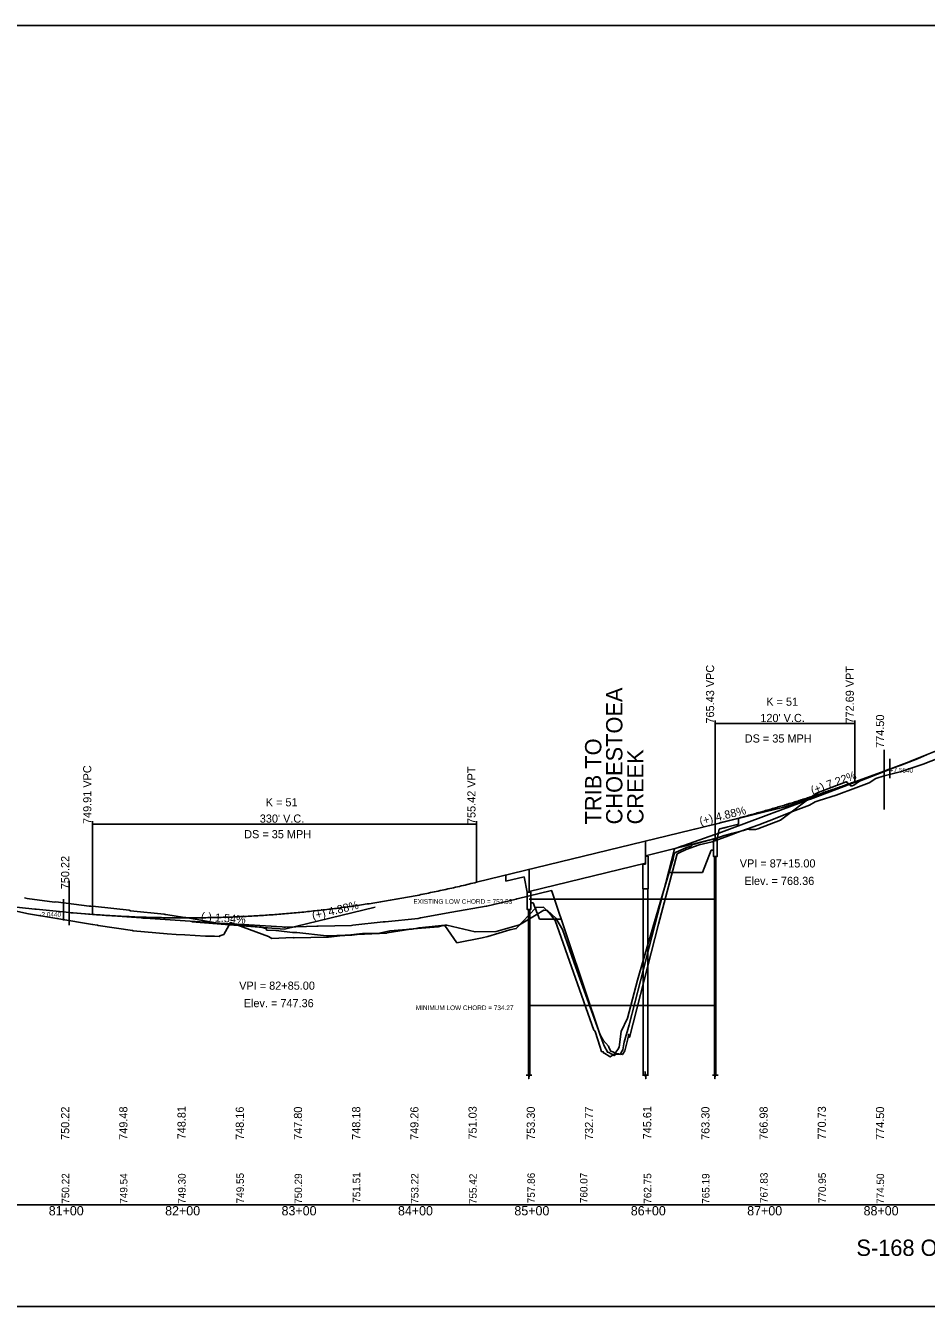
# Model space of a CAD drawing. Extents: x 1384070 to 1387149, y 1001217 to 1002317.
# Drawn here: x 1385108 to 1385882, y 1001217 to 1002317 of the extents above; entities that cross this region are included whole.
import ezdxf

# ---------------------------------------------------------------- set-up
doc = ezdxf.new("R2010")
doc.units = 0
for name, color, linetype in [('BR_EXIST_GROUND_LT', 7, 'Continuous'), ('BR_EXIST_GROUND_RT', 7, 'Continuous'), ('BR_GROUND LINES', 7, 'Continuous'), ('BR_USER NOTES', 7, 'Continuous'), ('RD_DDB_GradeTX', 7, 'Continuous'), ('RD_DDB_Profile_EX', 7, 'Continuous'), ('RD_DDB_Profile_Lbl', 7, 'Continuous'), ('RD_DDB_Profile_PR', 7, 'Continuous'), ('RD_DDB_StaTX', 7, 'Continuous'), ('RD_DDB_StripGrade', 7, 'Continuous'), ('RD_DDB_VCLbl', 7, 'Continuous'), ('RD_GPK_Profile_Cell', 7, 'Continuous'), ('RD_PD_Bridge', 7, 'Continuous'), ('RD_SHT_ShtClip', 7, 'Continuous'), ('RD_SHT_TX', 7, 'Continuous')]:
    doc.layers.add(name, color=color, linetype=linetype)

msp = doc.modelspace()

# ---------------------------------------------------------------- linework, layer by layer
at = {"layer": 'BR_EXIST_GROUND_LT'}
msp.add_lwpolyline([(1385107.5, 1001567.8), (1385109.7, 1001567.2), (1385133.1, 1001564.2), (1385134.3, 1001564.4), (1385163, 1001560.7), (1385164.3, 1001560.8), (1385168.4, 1001560.3), (1385197.2, 1001557.2), (1385198.3, 1001556.8), (1385227.3, 1001553.7), (1385228.3, 1001553.4), (1385228.9, 1001553.4), (1385244.9, 1001550.8), (1385246.1, 1001550.9), (1385274.9, 1001545.9), (1385275.3, 1001545.6), (1385284.3, 1001544.6), (1385288.2, 1001544.5), (1385310.3, 1001542.7), (1385314.6, 1001541.6), (1385315.6, 1001540), (1385323.2, 1001539.7), (1385326, 1001539.6), (1385337.6, 1001538.1), (1385341.2, 1001538.2), (1385366.8, 1001535.1), (1385368.5, 1001535.2), (1385382.8, 1001535.8), (1385388.7, 1001535.9), (1385393.2, 1001536.4), (1385418.5, 1001537.4), (1385419, 1001537.8), (1385438.9, 1001540.9), (1385440.4, 1001541), (1385446.3, 1001542.1), (1385468.4, 1001544.3), (1385470.2, 1001544.3), (1385494.5, 1001538.6), (1385512.7, 1001539), (1385532.6, 1001544.5), (1385546.9, 1001553.3), (1385553.4, 1001557.2), (1385556.6, 1001557), (1385563.7, 1001550.5), (1385569.4, 1001540.7), (1385579.5, 1001511.9), (1385601.9, 1001450.3), (1385604.5, 1001445.6), (1385609, 1001440.4), (1385609.6, 1001438.6), (1385611.1, 1001436.1), (1385612, 1001435.9), (1385612.9, 1001435.7), (1385615.5, 1001434), (1385620.3, 1001433.6), (1385621, 1001433.2), (1385621.6, 1001434), (1385623.2, 1001436.4), (1385625.6, 1001446.7), (1385626.1, 1001449.2), (1385626.3, 1001450.5), (1385627, 1001448), (1385651.9, 1001545.3), (1385668, 1001605.6), (1385669.9, 1001606.6), (1385675.9, 1001609.4), (1385686.8, 1001613.3), (1385698.2, 1001615.9), (1385712.2, 1001621.2), (1385722.6, 1001625), (1385738.1, 1001630.6), (1385752.2, 1001636.1), (1385767.2, 1001641.9), (1385781.8, 1001647.5), (1385786.7, 1001650.3), (1385789.9, 1001651.5), (1385804.6, 1001656.1), (1385821.5, 1001662.3), (1385833, 1001666.6), (1385838.8, 1001670.2), (1385846, 1001672.6), (1385861.9, 1001676.7), (1385862.3, 1001676.9), (1385879.4, 1001682.6), (1385892.5, 1001687.8)], dxfattribs=at)
at = {"layer": 'BR_EXIST_GROUND_RT'}
msp.add_lwpolyline([(1385080.9, 1001560.7), (1385109.4, 1001554.3), (1385110.8, 1001554.2), (1385135.1, 1001550.1), (1385135.8, 1001550), (1385136.8, 1001549.8), (1385165.9, 1001545), (1385170.1, 1001544.3), (1385170.7, 1001544.2), (1385200.1, 1001539.7), (1385200.8, 1001539.6), (1385230, 1001536.8), (1385237.8, 1001536.4), (1385245, 1001536.1), (1385262.9, 1001535), (1385270.7, 1001534.8), (1385275, 1001534.6), (1385275.1, 1001535.3), (1385278.6, 1001536.3), (1385284.2, 1001546.6), (1385316.9, 1001534.5), (1385319.8, 1001533), (1385332, 1001533.5), (1385338.1, 1001533.7), (1385338.5, 1001533.6), (1385338.9, 1001533.6), (1385367.6, 1001534.1), (1385368.6, 1001534.1), (1385380.9, 1001535.4), (1385382.5, 1001535.5), (1385397.7, 1001537.1), (1385412.2, 1001537.4), (1385421.2, 1001539.4), (1385435.4, 1001540.6), (1385437.7, 1001540.8), (1385462.7, 1001543), (1385467.1, 1001544), (1385468.6, 1001544.1), (1385478.9, 1001529.3), (1385500.4, 1001533.4), (1385505.4, 1001534.7), (1385524.2, 1001540.4), (1385529.8, 1001541.4), (1385546.5, 1001559.3), (1385547.3, 1001559.5), (1385553.2, 1001559.8), (1385554.3, 1001558.6), (1385560.2, 1001552.3), (1385563.2, 1001548.5), (1385596.5, 1001454.3), (1385597.2, 1001453.7), (1385598, 1001452.2), (1385601.5, 1001440.3), (1385602.9, 1001435.8), (1385604.5, 1001435.6), (1385604.9, 1001434.7), (1385606, 1001434.1), (1385609.7, 1001431.8), (1385610.6, 1001431.2), (1385614.9, 1001434.2), (1385615.4, 1001435.3), (1385617, 1001437.7), (1385618.1, 1001439.6), (1385620, 1001453), (1385625.3, 1001464.6), (1385628.3, 1001475.4), (1385633.9, 1001497.2), (1385638.8, 1001514), (1385655, 1001568.7), (1385664.6, 1001601.3), (1385665, 1001603.4), (1385665.7, 1001606.3), (1385666.6, 1001606.9), (1385676, 1001611), (1385680.2, 1001612.3), (1385681.6, 1001613.5), (1385695.5, 1001617.3), (1385705.3, 1001620.2), (1385708.4, 1001621.3), (1385709.9, 1001621.7), (1385714.8, 1001623.1), (1385724.9, 1001625.8), (1385728.5, 1001626.8), (1385729.9, 1001626.6), (1385735.3, 1001626.4), (1385737.3, 1001627.2), (1385756.8, 1001634.6), (1385786.9, 1001657.2), (1385789.3, 1001658.2), (1385813.1, 1001667.5), (1385817.2, 1001664.1), (1385818.4, 1001664), (1385819.9, 1001664.7), (1385824.6, 1001668.1), (1385850.4, 1001678.1), (1385853.9, 1001679.5), (1385859.6, 1001681.4), (1385874.5, 1001687.2), (1385882.8, 1001690.8)], dxfattribs=at)
at = {"layer": 'BR_GROUND LINES'}
for p, q in [((1385699.3, 1001608.7), (1385697.3, 1001608.7)), ((1385542.3, 1001563.6), (1385544.3, 1001563.6))]:
    msp.add_line(p, q, dxfattribs=at)
for points in [[(1385697.3, 1001608.7), (1385689.7, 1001589.6)], [(1385689.7, 1001589.6), (1385660.5, 1001589.6)], [(1385544.3, 1001563.6), (1385549.9, 1001549.6)], [(1385549.9, 1001549.6), (1385568.5, 1001549.6)]]:
    msp.add_lwpolyline(points, dxfattribs=at)
at = {"layer": 'BR_USER NOTES'}
for p, q in [((1385845.8, 1001694.9), (1385845.8, 1001643.6)), ((1385850.8, 1001687.2), (1385850.8, 1001670.6)), ((1385845.8, 1001676.6), (1385850.8, 1001678.5)), ((1385540.8, 1001575.6), (1385540.8, 1001591.9)), ((1385145.8, 1001582.4), (1385145.8, 1001544.4)), ((1385140.8, 1001566.8), (1385140.8, 1001548.4)), ((1385540.8, 1001566.7), (1385700.8, 1001566.7)), ((1385140.8, 1001555.7), (1385145.8, 1001555.2)), ((1385540.8, 1001475.4), (1385700.8, 1001475.4))]:
    msp.add_line(p, q, dxfattribs=at)
at = {"layer": 'RD_DDB_GradeTX'}
for p, q in [((1385836, 1001673), (1385760.8, 1001645.9)), ((1385683.1, 1001626.9), (1385760.8, 1001645.9)), ((1385408.5, 1001559.9), (1385330.8, 1001540.9)), ((1385251, 1001547.1), (1385330.8, 1001540.9))]:
    msp.add_line(p, q, dxfattribs=at)
at = {"layer": 'RD_DDB_Profile_EX'}
msp.add_lwpolyline([(1385087.3, 1001561.2), (1385116.2, 1001558.2), (1385117.3, 1001558.1), (1385145.9, 1001555.2), (1385147.3, 1001555), (1385148.9, 1001554.9), (1385178.2, 1001552.8), (1385178.9, 1001552.7), (1385207.6, 1001550.6), (1385208.9, 1001550.5), (1385211.1, 1001550.4), (1385223.9, 1001549.6), (1385241.1, 1001548.4), (1385271.1, 1001546.5), (1385275, 1001546.2), (1385299.5, 1001544.6), (1385300.2, 1001544.6), (1385328.8, 1001542.8), (1385330.2, 1001542.7), (1385331.5, 1001542.7), (1385358.4, 1001543.4), (1385359.7, 1001543.4), (1385388.4, 1001544.2), (1385389.5, 1001544.3), (1385415.6, 1001547.1), (1385417.3, 1001547.2), (1385445.6, 1001550.2), (1385447.6, 1001550.6), (1385474.4, 1001555.4), (1385504, 1001560.7), (1385504.4, 1001560.8), (1385529.8, 1001566.8), (1385530.2, 1001566.9), (1385530.6, 1001567), (1385560.2, 1001574), (1385560.6, 1001572.6), (1385601.9, 1001449.9), (1385605.3, 1001440.6), (1385608.5, 1001435), (1385608.6, 1001435.4), (1385609.4, 1001435.1), (1385611.3, 1001433.9), (1385614, 1001432.3), (1385615.7, 1001433.5), (1385619, 1001433.3), (1385620.3, 1001435.5), (1385621.3, 1001437.4), (1385622.3, 1001442.5), (1385622.6, 1001443.8), (1385626.9, 1001458.7), (1385665.8, 1001610), (1385671.7, 1001612.1), (1385673.9, 1001612.9), (1385700.5, 1001622.2), (1385701.6, 1001622.6), (1385719.8, 1001629.4), (1385720.6, 1001629.7), (1385749.1, 1001640.2), (1385750.6, 1001640.7), (1385751.4, 1001641), (1385780, 1001651.8), (1385781.3, 1001652.3), (1385782.5, 1001652.7), (1385811.2, 1001663.5), (1385837.4, 1001673.4), (1385838.4, 1001673.8), (1385867.2, 1001684.6), (1385868.4, 1001685.1), (1385869.9, 1001685.7), (1385898.6, 1001697.3)], dxfattribs=at)
at = {"layer": 'RD_DDB_Profile_PR'}
for p, q in [((1385820.8, 1001667.5), (1385845.8, 1001676.6)), ((1385495.8, 1001581.2), (1385700.8, 1001631.2)), ((1385145.8, 1001555.2), (1385165.8, 1001553.6))]:
    msp.add_line(p, q, dxfattribs=at)
for points in [[(1385700.8, 1001631.2), (1385703.2, 1001631.8), (1385705.6, 1001632.4), (1385708, 1001633), (1385710.4, 1001633.6), (1385712.8, 1001634.2), (1385715.2, 1001634.8), (1385717.6, 1001635.5), (1385720, 1001636.1), (1385722.4, 1001636.7), (1385724.8, 1001637.4), (1385727.2, 1001638), (1385729.6, 1001638.7), (1385732, 1001639.3), (1385734.4, 1001640), (1385736.8, 1001640.7), (1385739.2, 1001641.3), (1385741.6, 1001642), (1385744, 1001642.7), (1385746.4, 1001643.4), (1385748.8, 1001644.1), (1385751.2, 1001644.8), (1385753.6, 1001645.5), (1385756, 1001646.2), (1385758.4, 1001646.9), (1385760.8, 1001647.6), (1385763.2, 1001648.4), (1385765.6, 1001649.1), (1385768, 1001649.8), (1385770.4, 1001650.6), (1385772.8, 1001651.3), (1385775.2, 1001652.1), (1385777.6, 1001652.9), (1385780, 1001653.6), (1385782.4, 1001654.4), (1385784.8, 1001655.2), (1385787.2, 1001656), (1385789.6, 1001656.8), (1385792, 1001657.5), (1385794.4, 1001658.3), (1385796.8, 1001659.2), (1385799.2, 1001660), (1385801.6, 1001660.8), (1385804, 1001661.6), (1385806.4, 1001662.4), (1385808.8, 1001663.3), (1385811.2, 1001664.1), (1385813.6, 1001665), (1385816, 1001665.8), (1385818.4, 1001666.7), (1385820.8, 1001667.5)], [(1385165.8, 1001553.6), (1385172.4, 1001553.1), (1385179, 1001552.7), (1385185.6, 1001552.3), (1385192.2, 1001551.9), (1385198.8, 1001551.6), (1385205.4, 1001551.3), (1385212, 1001551.1), (1385218.6, 1001550.9), (1385225.2, 1001550.8), (1385231.8, 1001550.7), (1385238.4, 1001550.6), (1385245, 1001550.6), (1385251.6, 1001550.6), (1385258.2, 1001550.7), (1385264.8, 1001550.8), (1385271.4, 1001550.9), (1385278, 1001551.1), (1385284.6, 1001551.3), (1385291.2, 1001551.6), (1385297.8, 1001551.9), (1385304.4, 1001552.3), (1385311, 1001552.7), (1385317.6, 1001553.1), (1385324.2, 1001553.6), (1385330.8, 1001554.1), (1385337.4, 1001554.7), (1385344, 1001555.3), (1385350.6, 1001556), (1385357.2, 1001556.7), (1385363.8, 1001557.4), (1385370.4, 1001558.2), (1385377, 1001559), (1385383.6, 1001559.9), (1385390.2, 1001560.8), (1385396.8, 1001561.8), (1385403.4, 1001562.8), (1385410, 1001563.8), (1385416.6, 1001564.9), (1385423.2, 1001566), (1385429.8, 1001567.2), (1385436.4, 1001568.4), (1385443, 1001569.6), (1385449.6, 1001570.9), (1385456.2, 1001572.3), (1385462.8, 1001573.7), (1385469.4, 1001575.1), (1385476, 1001576.5), (1385482.6, 1001578), (1385489.2, 1001579.6), (1385495.8, 1001581.2)]]:
    msp.add_spline(points, degree=3, dxfattribs=at)
at = {"layer": 'RD_DDB_VCLbl'}
for p, q in [((1385700.8, 1001720), (1385700.8, 1001631.2)), ((1385700.8, 1001717.5), (1385820.8, 1001717.5)), ((1385820.8, 1001720), (1385820.8, 1001667.5)), ((1385165.8, 1001633.7), (1385165.8, 1001553.6)), ((1385165.8, 1001631.2), (1385495.8, 1001631.2)), ((1385495.8, 1001633.7), (1385495.8, 1001581.2))]:
    msp.add_line(p, q, dxfattribs=at)
at = {"layer": 'RD_GPK_Profile_Cell'}
msp.add_line((1384153.6, 1001304.1), (1387149.1, 1001304.1), dxfattribs=at)
at = {"layer": 'RD_PD_Bridge'}
for p, q in [((1385700.8, 1001618.7), (1385700.8, 1001631.2)), ((1385720.8, 1001631.1), (1385720.8, 1001636.3)), ((1385640.8, 1001604), (1385700.8, 1001618.7)), ((1385640.8, 1001597.6), (1385640.8, 1001616.6)), ((1385700.8, 1001618.7), (1385700.8, 1001618.2)), ((1385702.3, 1001618.2), (1385704, 1001626.9)), ((1385540.8, 1001573.2), (1385640.8, 1001597.6)), ((1385640.8, 1001604), (1385640.8, 1001603.6)), ((1385700.2, 1001603.2), (1385700.2, 1001415.4)), ((1385701.4, 1001603.2), (1385701.4, 1001415.4)), ((1385520.8, 1001587.3), (1385520.8, 1001582.1)), ((1385520.8, 1001582.1), (1385536.6, 1001586)), ((1385539.3, 1001572.7), (1385536.6, 1001586)), ((1385540.8, 1001573.2), (1385540.8, 1001592.2)), ((1385540.8, 1001573.1), (1385540.8, 1001572.7)), ((1385638.8, 1001415.4), (1385638.8, 1001575.7)), ((1385642.8, 1001415.4), (1385642.8, 1001575.7)), ((1385540.2, 1001557.7), (1385540.2, 1001415.4)), ((1385541.4, 1001557.7), (1385541.4, 1001415.4))]:
    msp.add_line(p, q, dxfattribs=at)
for points in [[(1385702.3, 1001618.2), (1385699.3, 1001618.2), (1385699.3, 1001603.2), (1385702.3, 1001603.2)], [(1385640.8, 1001596.7), (1385638.5, 1001596.7), (1385638.5, 1001575.7), (1385643, 1001575.7), (1385643, 1001603.6), (1385640.8, 1001603.6)], [(1385539.3, 1001572.7), (1385542.3, 1001572.7), (1385542.3, 1001557.7), (1385539.3, 1001557.7)]]:
    msp.add_lwpolyline(points, close=True, dxfattribs=at)
for points in [[(1385538.3, 1001415.4), (1385540.5, 1001415.4), (1385540.5, 1001412.4), (1385541.1, 1001418.4), (1385541.1, 1001415.4), (1385543.2, 1001415.4)], [(1385643.3, 1001415.4), (1385641.1, 1001415.4), (1385641.1, 1001412.4), (1385640.5, 1001418.4), (1385640.5, 1001415.4), (1385638.4, 1001415.4)], [(1385698.3, 1001415.4), (1385700.5, 1001415.4), (1385700.5, 1001412.4), (1385701.1, 1001418.4), (1385701.1, 1001415.4), (1385703.2, 1001415.4)]]:
    msp.add_lwpolyline(points, dxfattribs=at)
msp.add_open_spline([(1385704, 1001626.9), (1385704.1, 1001626.9), (1385704.2, 1001626.9), (1385704.4, 1001627), (1385704.4, 1001627), (1385704.4, 1001627), (1385704.4, 1001627), (1385704.5, 1001627), (1385704.6, 1001627), (1385704.8, 1001627.1), (1385705.2, 1001627.2), (1385705.8, 1001627.3), (1385706.4, 1001627.5), (1385706.8, 1001627.6), (1385706.9, 1001627.6), (1385707.1, 1001627.6), (1385707.3, 1001627.7), (1385708.2, 1001627.9), (1385711.5, 1001628.7), (1385715.9, 1001629.9), (1385719.6, 1001630.8), (1385720.8, 1001631.1)], degree=3, dxfattribs=at)
at = {"layer": 'RD_SHT_ShtClip'}
msp.add_lwpolyline([(1384516.2, 1002316.9), (1386316.2, 1002316.9), (1386316.2, 1001216.9), (1384516.2, 1001216.9)], close=True, dxfattribs=at)

# ---------------------------------------------------------------- texts
at = {"layer": 'BR_USER NOTES'}
for s, p in [('+7.5540', (1385850.6, 1001675.4)), ('EXISTING LOW CHORD = 752.53', (1385441.5, 1001562.7)), ('-2.0440', (1385120.1, 1001551.6)), ('MINIMUM LOW CHORD = 734.27', (1385443.5, 1001471.4))]:
    msp.add_text(s, height=4, dxfattribs=at).set_placement(p)
at = {"layer": 'RD_DDB_GradeTX'}
for s, rotation, p in [('(+) 7.22%', 19.8496, (1385784.3, 1001656.5)), ('(+) 4.88%', 13.7208, (1385688.1, 1001630.2)), ('(+) 4.88%', 13.7208, (1385355.3, 1001548.9)), ('(-) 1.54%', 355.5855, (1385258.8, 1001548.5))]:
    msp.add_text(s, height=7, rotation=rotation, dxfattribs=at).set_placement(p)
at = {"layer": 'RD_DDB_Profile_Lbl'}
for s, p in [('774.50', (1385845.8, 1001696.6)), ('750.22', (1385145.8, 1001575.2))]:
    msp.add_text(s, height=7, rotation=90, dxfattribs=at).set_placement(p)
for s, p in [('VPI = 87+15.00', (1385721.8, 1001593.9)), ('Elev. = 768.36', (1385725.7, 1001578.9)), ('VPI = 82+85.00', (1385291.8, 1001488.9)), ('Elev. = 747.36', (1385295.7, 1001473.9))]:
    msp.add_text(s, height=7, dxfattribs=at).set_placement(p)
at = {"layer": 'RD_DDB_StaTX'}
for s, p in [('81+00', (1385128.2, 1001295.1)), ('82+00', (1385228.2, 1001295.1)), ('83+00', (1385328.2, 1001295.1)), ('84+00', (1385428.2, 1001295.1)), ('85+00', (1385528.2, 1001295.1)), ('86+00', (1385628.2, 1001295.1)), ('87+00', (1385728.2, 1001295.1)), ('88+00', (1385828.2, 1001295.1))]:
    msp.add_text(s, height=8, dxfattribs=at).set_placement(p)
at = {"layer": 'RD_DDB_StripGrade'}
for s, height, p in [('765.43 VPC', 7, (1385699.8, 1001717.5)), ('772.69 VPT', 7, (1385819.8, 1001717.5)), ('749.91 VPC', 7, (1385164.8, 1001631.2)), ('755.42 VPT', 7, (1385494.8, 1001631.2)), ('750.22', 7, (1385145.8, 1001359.9)), ('749.48', 7, (1385195.8, 1001360)), ('748.81', 7, (1385245.8, 1001360.4)), ('748.16', 7, (1385295.8, 1001359.9)), ('747.80', 7, (1385345.8, 1001359.9)), ('748.18', 7, (1385395.8, 1001360)), ('749.26', 7, (1385445.8, 1001359.9)), ('751.03', 7, (1385495.8, 1001360.2)), ('753.30', 7, (1385545.8, 1001359.9)), ('732.77', 7, (1385595.8, 1001359.9)), ('745.61', 7, (1385645.8, 1001360.4)), ('763.30', 7, (1385695.8, 1001359.9)), ('766.98', 7, (1385745.8, 1001360)), ('770.73', 7, (1385795.8, 1001360.2)), ('774.50', 7, (1385845.8, 1001359.9)), ('750.22', 6.4, (1385145.8, 1001305.1)), ('749.54', 6.4, (1385195.8, 1001305.1)), ('749.30', 6.4, (1385245.8, 1001305)), ('749.55', 6.4, (1385295.8, 1001305.4)), ('750.29', 6.4, (1385345.8, 1001305)), ('751.51', 6.4, (1385395.8, 1001305.9)), ('753.22', 6.4, (1385445.8, 1001305.1)), ('755.42', 6.4, (1385495.8, 1001304.8)), ('757.86', 6.4, (1385545.8, 1001305.5)), ('760.07', 6.4, (1385591, 1001305.6)), ('762.75', 6.4, (1385645.8, 1001305.1)), ('765.19', 6.4, (1385695.8, 1001305)), ('767.83', 6.4, (1385745.8, 1001305.7)), ('770.95', 6.4, (1385795.8, 1001305.6)), ('774.50', 6.4, (1385845.8, 1001304.9))]:
    msp.add_text(s, height=height, rotation=90, dxfattribs=at).set_placement(p)
at = {"layer": 'RD_DDB_VCLbl'}
for s, p in [('K = 51', (1385744.6, 1001732.8)), ("120' V.C.", (1385739.5, 1001718.8)), ('DS = 35 MPH', (1385726.1, 1001701.2)), ('K = 51', (1385314.6, 1001646.4)), ("330' V.C.", (1385309.5, 1001632.4)), ('DS = 35 MPH', (1385296.1, 1001619))]:
    msp.add_text(s, height=7, dxfattribs=at).set_placement(p)
at = {"layer": 'RD_SHT_TX'}
for s, rotation, p in [('CHOESTOEA ', 90, (1385621, 1001630.9)), ('TRIB TO ', 90, (1385602.9, 1001630.9)), ('CREEK', 90, (1385639.1, 1001630.9)), ('S-168 OVER TRIBUTARY TO CHOESTOEA CREEK', 360, (1385822, 1001260.3))]:
    msp.add_text(s, height=14, rotation=rotation, dxfattribs=at).set_placement(p)

doc.saveas('drawing.dxf')
